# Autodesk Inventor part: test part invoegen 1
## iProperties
Created: 2009-12
Part Number: test part invoegen 1
Document SubType Name: Modeling
Designer: Guido
Mass: 21.8584 g
Surface Area: 70 cm^2
Volume: 21.8584 cm^3
Density: 1 g/cm^3
Description: Part met gat
Author: Guido
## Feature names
1. Extrusion1
2. Hole1
3. Rectangular Pattern1
